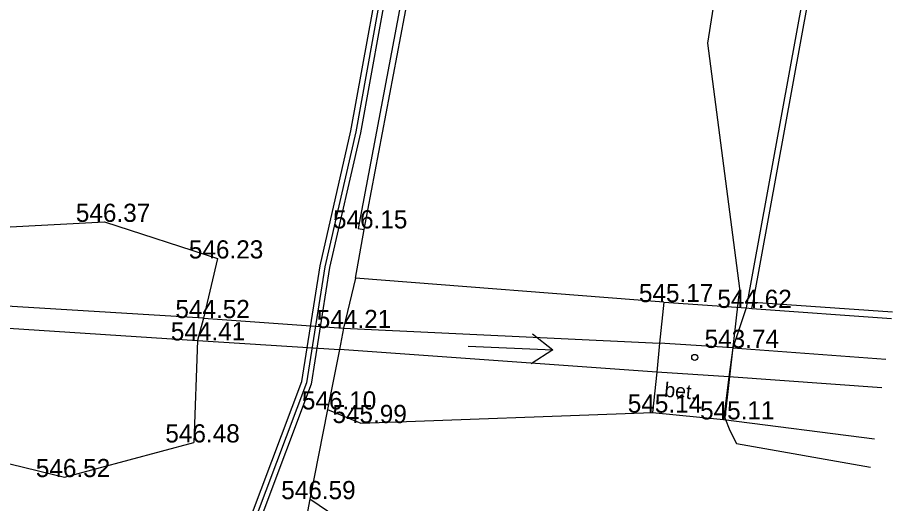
# Model space of a CAD drawing. Extents: x -669995 to -669686, y -1125551 to -1125263.
# Drawn here: x -669732.62 to -669696.55, y -1125382.34 to -1125362.29 of the extents above; entities that cross this region are included whole.
import ezdxf

# ---------------------------------------------------------------- set-up
doc = ezdxf.new("R2010")
doc.units = 0
for name, color, linetype in [('G_Bod_tecka', 7, 'Continuous'), ('G_Bod_vyska', 7, 'Continuous'), ('G_Breh_Teren', 7, 'Continuous'), ('G_Budovy-znacky', 7, 'Continuous'), ('G_Budovy_Objekty', 7, 'Continuous'), ('G_Ploty', 7, 'Continuous'), ('G_Ploty_vstupy', 7, 'Continuous'), ('G_Popisy_Nazvy', 7, 'Continuous'), ('G_Popisy_povrchu', 7, 'Continuous'), ('G_Z_CHRANICKA-TEPLOVOD_kotovane', 7, 'Continuous'), ('G_Z_ELsilove_podz_kotovane', 7, 'Continuous'), ('G_Z_SPOJE_podz_geodeticky', 7, 'Continuous'), ('G_Z_SPOJE_podz_kotovane', 7, 'Continuous'), ('G_Z_SPOJE_podz_priblizne', 7, 'Continuous')]:
    doc.layers.add(name, color=color, linetype=linetype)

msp = doc.modelspace()

# ---------------------------------------------------------------- linework, layer by layer
at = {"layer": 'G_Bod_tecka'}
for p, q in [((-669729.04, -1125370.72), (-669729.04, -1125370.72)), ((-669718.58, -1125370.99), (-669718.58, -1125370.99)), ((-669724.38, -1125372.23), (-669724.38, -1125372.23)), ((-669705.98, -1125374.03), (-669705.98, -1125374.03)), ((-669702.59, -1125374.27), (-669702.59, -1125374.27)), ((-669724.95, -1125374.69), (-669724.95, -1125374.69)), ((-669719.18, -1125375.1), (-669719.18, -1125375.1)), ((-669725.2, -1125375.61), (-669725.2, -1125375.61)), ((-669703.13, -1125375.92), (-669703.13, -1125375.92)), ((-669719.84, -1125378.46), (-669719.84, -1125378.46)), ((-669706.44, -1125378.59), (-669706.44, -1125378.59)), ((-669703.52, -1125378.87), (-669703.52, -1125378.87)), ((-669718.47, -1125379.02), (-669718.47, -1125379.02)), ((-669725.35, -1125379.82), (-669725.35, -1125379.82)), ((-669730.69, -1125381.25), (-669730.69, -1125381.25)), ((-669720.57, -1125382.16), (-669720.57, -1125382.16))]:
    msp.add_line(p, q, dxfattribs=at)
at = {"layer": 'G_Breh_Teren'}
for p, q in [((-669749.54, -1125371.81), (-669729.04, -1125370.72)), ((-669729.04, -1125370.72), (-669724.38, -1125372.23)), ((-669724.38, -1125372.23), (-669724.95, -1125374.69)), ((-669724.95, -1125374.69), (-669725.2, -1125375.61)), ((-669724.95, -1125374.69), (-669719.18, -1125375.1)), ((-669719.18, -1125375.1), (-669706.15, -1125375.72)), ((-669725.2, -1125375.61), (-669725.35, -1125379.82)), ((-669725.2, -1125375.61), (-669719.35, -1125375.98)), ((-669706.27, -1125376.92), (-669719.35, -1125375.98)), ((-669703.13, -1125375.92), (-669706.15, -1125375.72)), ((-669703.13, -1125375.92), (-669696.822, -1125376.384)), ((-669750.09, -1125376.5), (-669730.69, -1125381.25)), ((-669703.29, -1125377.11), (-669706.27, -1125376.92)), ((-669696.991, -1125377.567), (-669703.29, -1125377.11)), ((-669719.84, -1125378.46), (-669718.47, -1125379.02)), ((-669718.47, -1125379.02), (-669706.44, -1125378.59)), ((-669706.44, -1125378.59), (-669703.52, -1125378.87)), ((-669703.52, -1125378.87), (-669697.29, -1125379.67)), ((-669730.69, -1125381.25), (-669725.35, -1125379.82)), ((-669707.41, -1125391.03), (-669720.57, -1125382.16))]:
    msp.add_line(p, q, dxfattribs=at)
for points in [[(-669724.95, -1125374.69), (-669749.78, -1125373.18)], [(-669749.86, -1125374), (-669725.2, -1125375.61)]]:
    msp.add_lwpolyline(points, dxfattribs=at)
at = {"layer": 'G_Budovy-znacky'}
msp.add_circle((-669704.7, -1125376.311), 0.125, dxfattribs=at)
at = {"layer": 'G_Budovy_Objekty'}
for p, q in [((-669705.98, -1125374.03), (-669706.15, -1125375.72)), ((-669702.58, -1125374.27), (-669703.13, -1125375.92)), ((-669706.15, -1125375.72), (-669706.27, -1125376.92)), ((-669703.13, -1125375.92), (-669703.29, -1125377.11)), ((-669706.27, -1125376.92), (-669706.44, -1125378.59)), ((-669703.29, -1125377.11), (-669703.52, -1125378.87))]:
    msp.add_line(p, q, dxfattribs=at)
at = {"layer": 'G_Ploty'}
for p, q in [((-669714.14, -1125347.48), (-669718.58, -1125370.99)), ((-669718.33, -1125371.04), (-669713.94, -1125347.77)), ((-669698.25, -1125350.49), (-669702.58, -1125374.27)), ((-669702.29, -1125374.04), (-669698, -1125350.53)), ((-669718.58, -1125370.99), (-669718.33, -1125371.04)), ((-669718.69, -1125373.04), (-669718.33, -1125371.04)), ((-669718.69, -1125373.04), (-669719.18, -1125375.1)), ((-669705.98, -1125374.03), (-669718.69, -1125373.04)), ((-669702.34, -1125374.29), (-669702.29, -1125374.04)), ((-669696.546, -1125374.446), (-669702.29, -1125374.04)), ((-669702.58, -1125374.27), (-669702.34, -1125374.29)), ((-669702.34, -1125374.29), (-669696.583, -1125374.702)), ((-669719.18, -1125375.1), (-669719.35, -1125375.98)), ((-669719.35, -1125375.98), (-669719.84, -1125378.46)), ((-669719.84, -1125378.46), (-669720.57, -1125382.16)), ((-669720.57, -1125382.16), (-669723.17, -1125395.96))]:
    msp.add_line(p, q, dxfattribs=at)
at = {"layer": 'G_Ploty_vstupy'}
msp.add_line((-669705.98, -1125374.03), (-669702.58, -1125374.27), dxfattribs=at)
at = {"layer": 'G_Popisy_Nazvy'}
for p, q in [((-669711.39, -1125375.34), (-669710.55, -1125376)), ((-669714.047, -1125375.842), (-669710.55, -1125376)), ((-669710.55, -1125376), (-669711.447, -1125376.581))]:
    msp.add_line(p, q, dxfattribs=at)
at = {"layer": 'G_Z_CHRANICKA-TEPLOVOD_kotovane'}
msp.add_lwpolyline([(-669725.327, -1125392.473), (-669724.624, -1125389.742), (-669722.972, -1125382.821), (-669720.904, -1125377.309), (-669720.146, -1125372.532), (-669718.876, -1125366.96), (-669717.277, -1125358.154), (-669717.078, -1125358.19), (-669716.883, -1125358.226), (-669716.883, -1125358.227), (-669718.484, -1125367.04), (-669719.754, -1125372.608), (-669720.516, -1125377.411), (-669722.588, -1125382.939), (-669724.236, -1125389.838), (-669724.946, -1125392.6), (-669725.14, -1125392.55), (-669725.334, -1125392.5)], close=True, dxfattribs=at)
at = {"layer": 'G_Z_ELsilove_podz_kotovane'}
msp.add_lwpolyline([(-669713.55, -1125347.24), (-669713.633, -1125346.997), (-669714.81, -1125347.42), (-669715.78, -1125351.89), (-669716.49, -1125355.02), (-669717.08, -1125358.19), (-669717.768, -1125361.979), (-669718.68, -1125367), (-669719.95, -1125372.57), (-669720.71, -1125377.36), (-669722.78, -1125382.88)], dxfattribs=at)
at = {"layer": 'G_Z_SPOJE_podz_geodeticky'}
msp.add_lwpolyline([(-669705.85, -1125358), (-669704.5, -1125358.21), (-669703.4, -1125358.44), (-669704.18, -1125363.34), (-669702.86, -1125373.47), (-669703.46, -1125378.8), (-669703.26, -1125379.33), (-669702.98, -1125379.87), (-669697.457, -1125380.845)], dxfattribs=at)
at = {"layer": 'G_Z_SPOJE_podz_kotovane'}
msp.add_lwpolyline([(-669705.85, -1125358), (-669704.5, -1125358.21), (-669703.4, -1125358.44), (-669704.18, -1125363.34), (-669702.86, -1125373.47), (-669703.46, -1125378.8), (-669703.26, -1125379.33), (-669702.98, -1125379.87), (-669697.457, -1125380.845)], dxfattribs=at)
at = {"layer": 'G_Z_SPOJE_podz_priblizne'}
msp.add_lwpolyline([(-669705.85, -1125358), (-669704.5, -1125358.21), (-669703.4, -1125358.44), (-669704.18, -1125363.34), (-669702.86, -1125373.47), (-669703.46, -1125378.8), (-669703.26, -1125379.33), (-669702.98, -1125379.87), (-669697.457, -1125380.845)], dxfattribs=at)

# ---------------------------------------------------------------- texts
at = {"layer": 'G_Bod_vyska'}
for s, p in [('546.37', (-669730.218, -1125370.72)), ('546.15', (-669719.616, -1125370.99)), ('546.23', (-669725.558, -1125372.23)), ('545.17', (-669707.002, -1125374.03)), ('544.62', (-669703.768, -1125374.27)), ('544.52', (-669726.114, -1125374.69)), ('544.21', (-669720.282, -1125375.1)), ('544.41', (-669726.302, -1125375.61)), ('543.74', (-669704.294, -1125375.92)), ('546.10', (-669720.898, -1125378.46)), ('545.14', (-669707.462, -1125378.59)), ('545.11', (-669704.481, -1125378.87)), ('545.99', (-669719.638, -1125379.02)), ('546.48', (-669726.528, -1125379.82)), ('546.52', (-669731.868, -1125381.25)), ('546.59', (-669721.75, -1125382.16))]:
    msp.add_text(s, height=0.75, dxfattribs=at).set_placement(p)
at = {"layer": 'G_Popisy_povrchu'}
msp.add_text('bet.', height=0.6, rotation=354.5476, dxfattribs=at).set_placement((-669705.975, -1125377.931))

doc.saveas('drawing.dxf')
